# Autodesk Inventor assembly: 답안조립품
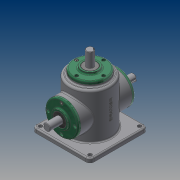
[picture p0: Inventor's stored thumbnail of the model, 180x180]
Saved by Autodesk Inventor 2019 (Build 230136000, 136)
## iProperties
Created: 2019-03
Part Number: 답안조립품
Material: 일반
Document SubType Name: Assembly
Designer: PC312-14
Author: PC312-14
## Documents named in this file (16)
- C:\Users\PC312-14\Desktop\490314V1008\답안조립품.iam
- C:\Users\PC312-14\Desktop\490314V1008\본체.ipt
- C:\Users\PC312-14\Desktop\490314V1008\커버.ipt
- C:\Users\PC312-14\Desktop\490314V1008\베어링 6203.ipt
- C:\Users\PC312-14\Desktop\490314V1008\오일 실.ipt
- 오일 실.ipt
- C:\Users\PC312-14\Desktop\490314V1008\메인 축.ipt
- 메인 축.ipt
- C:\Users\PC312-14\Desktop\490314V1008\키 5x5.ipt
- C:\Users\PC312-14\Desktop\490314V1008\키 4x4.ipt
- C:\Users\PC312-14\Desktop\490314V1008\서브 축.ipt
- 서브 축.ipt
- C:\Users\PC312-14\Desktop\490314V1008\메인 베벨기어.ipt
- C:\Users\PC312-14\Desktop\490314V1008\서브 베벨기어.ipt
- C:\Users\PC312-14\Desktop\490314V1008\볼트 M4.ipt
- 볼트 M4.ipt
